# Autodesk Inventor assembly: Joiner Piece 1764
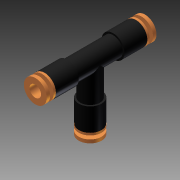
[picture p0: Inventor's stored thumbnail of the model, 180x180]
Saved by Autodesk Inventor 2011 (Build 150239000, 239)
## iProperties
Created: 2010-02
Part Number: Joiner Piece 1764
Document SubType Name: Assembly
Designer: jgehrig
Author: jgehrig
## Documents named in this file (3)
- R:\CAD Archives\Pnewmatics\Joiner Piece\Joiner Piece 1764.iam
- R:\CAD Archives\Pnewmatics\Joiner Piece\Joiner Base 1764.ipt
- R:\CAD Archives\Pnewmatics\Joiner Piece\Pnewmatic Screw Part 2 1764.ipt
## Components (4 placed, 2 different names)
1. Joiner Base 1764:1 — Insert:1, Insert:2, Insert:3
2. Pnewmatic Screw Part 2 1764:1 — Insert:3
3. Pnewmatic Screw Part 2 1764:2 — Insert:2
4. Pnewmatic Screw Part 2 1764:3 — Insert:1
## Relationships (3: Insert 3)
- Insert:1: Joiner Base 1764:1 ↔ Pnewmatic Screw Part 2 1764:3
- Insert:2: Joiner Base 1764:1 ↔ Pnewmatic Screw Part 2 1764:2
- Insert:3: Joiner Base 1764:1 ↔ Pnewmatic Screw Part 2 1764:1
